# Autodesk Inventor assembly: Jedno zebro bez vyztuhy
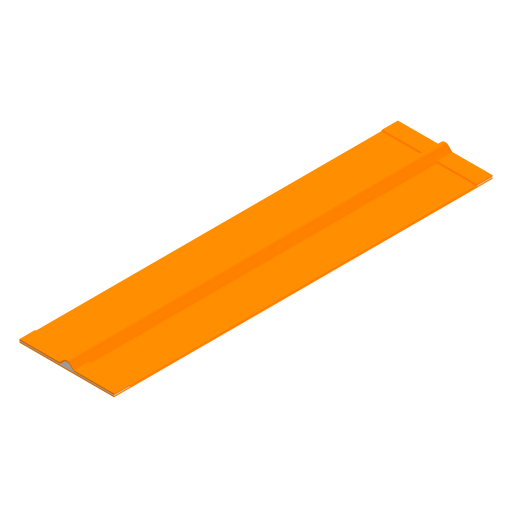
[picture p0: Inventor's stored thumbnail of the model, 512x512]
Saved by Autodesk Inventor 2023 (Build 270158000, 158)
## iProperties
Created: 2025-03
Part Number: Jedno zebro bez vyztuhy
Document SubType Name: Assembly
Designer: tomik
Author: tomik
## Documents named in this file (4)
- C:\Users\tomik\Desktop\Růčka_Tomáš_přílohy\Vyztužení\Jedno žebro\Jedno zebro .iam
- C:\Users\tomik\Desktop\Růčka_Tomáš_přílohy\Vyztužení\Jedno žebro\Spodni tkanina 50x200.ipt
- C:\Users\tomik\Desktop\Růčka_Tomáš_přílohy\Vyztužení\Jedno žebro\Zebro_jedno.ipt
- C:\Users\tomik\Desktop\Růčka_Tomáš_přílohy\Vyztužení\Jedno žebro\Horni tkanina.ipt
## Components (3 placed, 3 different names)
1. Spodni tkanina 50x200:1 — Proti sobě:1, Proti sobě:2, Stejný směr:1, Proti sobě:3, Stejný směr:2, Proti sobě:4, Proti sobě:5
2. Zebro_jedno:1 — Proti sobě:3, Stejný směr:2, Proti sobě:4, Proti sobě:6, Proti sobě:7
3. Horni tkanina:1 — Proti sobě:5, Proti sobě:6, Proti sobě:7, Stejný směr:3
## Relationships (10: Mate 7, Flush 3)
- Proti sobě:1 [Mate]: Spodni tkanina 50x200:1
- Proti sobě:2 [Mate]: Spodni tkanina 50x200:1
- Stejný směr:1 [Flush]: Spodni tkanina 50x200:1
- Proti sobě:3 [Mate]: Spodni tkanina 50x200:1 ↔ Zebro_jedno:1
- Stejný směr:2 [Flush]: Spodni tkanina 50x200:1 ↔ Zebro_jedno:1
- Proti sobě:4 [Mate]: Spodni tkanina 50x200:1 ↔ Zebro_jedno:1
- Proti sobě:5 [Mate]: Spodni tkanina 50x200:1 ↔ Horni tkanina:1
- Proti sobě:6 [Mate]: Zebro_jedno:1 ↔ Horni tkanina:1
- Proti sobě:7 [Mate]: Zebro_jedno:1 ↔ Horni tkanina:1
- Stejný směr:3 [Flush]: Horni tkanina:1
